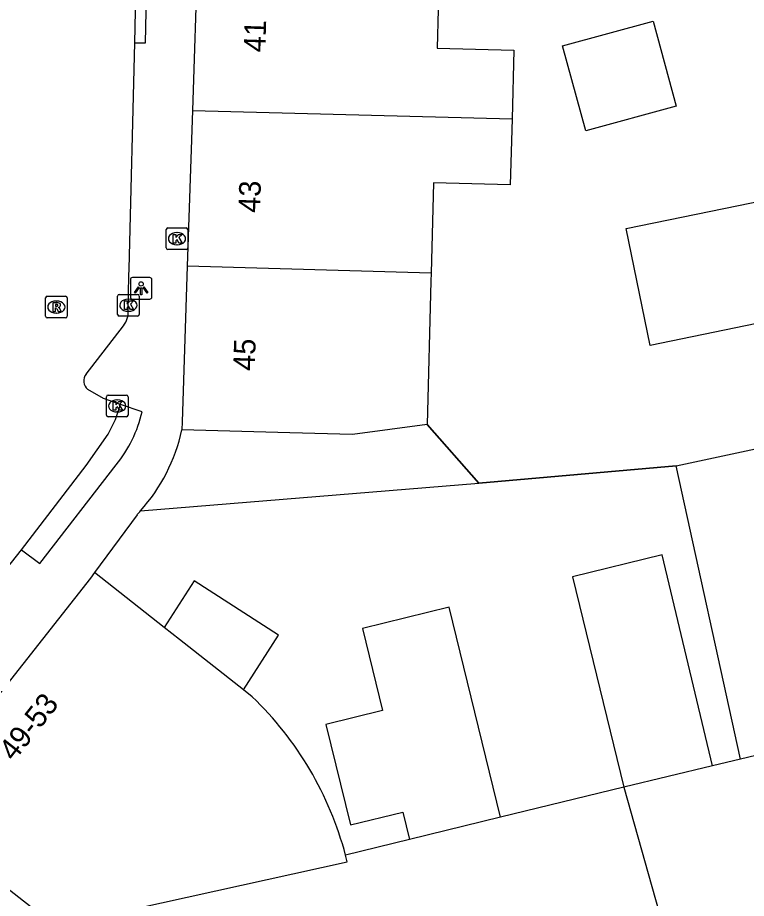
# Model space of a CAD drawing. Extents: x 162074 to 163034, y 381824 to 382557.
# Drawn here: x 162219.38 to 162253.14, y 382105.9 to 382146.68 of the extents above; entities that cross this region are included whole.
import ezdxf

# ---------------------------------------------------------------- set-up
doc = ezdxf.new("R2010")
doc.units = 0
for name, color, linetype in [('IMGEO_Hek', 7, 'Continuous'), ('IMGEO_Kolk', 7, 'Continuous'), ('IMGEO_Lichtpunt', 7, 'Continuous'), ('IMGEO_Pand', 7, 'Continuous'), ('IMGEO_Pand_nummerreeks', 7, 'Continuous'), ('IMGEO_Rijbaan_lokaal_open', 7, 'Continuous'), ('IMGEO_Rioolput', 7, 'Continuous'), ('IMGEO_Voetpad_open', 7, 'Continuous')]:
    doc.layers.add(name, color=color, linetype=linetype)

msp = doc.modelspace()

# ---------------------------------------------------------------- linework, layer by layer
at = {"layer": 'IMGEO_Hek'}
msp.add_lwpolyline([(162249.896, 382125.928), (162240.742, 382125.127), (162238.357, 382127.847)], dxfattribs=at)
at = {"layer": 'IMGEO_Kolk'}
for p, q in [((162226.267, 382136.018), (162226.267, 382136.87)), ((162226.342, 382136.944), (162227.194, 382136.944)), ((162226.755, 382136.724), (162226.78, 382136.724)), ((162227.268, 382136.87), (162227.268, 382136.018)), ((162227.194, 382135.944), (162226.342, 382135.944)), ((162226.778, 382136.164), (162226.753, 382136.164)), ((162224.089, 382133.862), (162224.941, 382133.862)), ((162224.014, 382132.936), (162224.014, 382133.788)), ((162224.502, 382133.642), (162224.527, 382133.642)), ((162225.015, 382133.788), (162225.015, 382132.936)), ((162224.525, 382133.082), (162224.5, 382133.082)), ((162224.941, 382132.862), (162224.089, 382132.862)), ((162223.497, 382128.274), (162223.497, 382129.126)), ((162223.572, 382129.2), (162224.424, 382129.2)), ((162223.985, 382128.98), (162224.01, 382128.98)), ((162224.498, 382129.126), (162224.498, 382128.274)), ((162224.424, 382128.2), (162223.572, 382128.2)), ((162224.008, 382128.42), (162223.983, 382128.42))]:
    msp.add_line(p, q, dxfattribs=at)
for points in [[(162226.267, 382136.018), (162226.267, 382136.87)], [(162226.342, 382136.944), (162227.194, 382136.944)], [(162227.268, 382136.87), (162227.268, 382136.018)], [(162226.588, 382136.644), (162226.711, 382136.644), (162226.711, 382136.493), (162226.841, 382136.644), (162227.005, 382136.644), (162226.859, 382136.493), (162227.012, 382136.244), (162226.86, 382136.244), (162226.775, 382136.408), (162226.711, 382136.341), (162226.711, 382136.244), (162226.588, 382136.244), (162226.588, 382136.644)], [(162227.194, 382135.944), (162226.342, 382135.944)], [(162224.089, 382133.862), (162224.941, 382133.862)], [(162224.014, 382132.936), (162224.014, 382133.788)], [(162224.335, 382133.562), (162224.458, 382133.562), (162224.458, 382133.411), (162224.588, 382133.562), (162224.752, 382133.562), (162224.606, 382133.411), (162224.759, 382133.162), (162224.607, 382133.162), (162224.522, 382133.326), (162224.458, 382133.259), (162224.458, 382133.162), (162224.335, 382133.162), (162224.335, 382133.562)], [(162225.015, 382133.788), (162225.015, 382132.936)], [(162224.941, 382132.862), (162224.089, 382132.862)], [(162223.497, 382128.274), (162223.497, 382129.126)], [(162223.572, 382129.2), (162224.424, 382129.2)], [(162224.498, 382129.126), (162224.498, 382128.274)], [(162223.818, 382128.9), (162223.941, 382128.9), (162223.941, 382128.749), (162224.071, 382128.9), (162224.235, 382128.9), (162224.089, 382128.749), (162224.242, 382128.5), (162224.09, 382128.5), (162224.005, 382128.664), (162223.941, 382128.597), (162223.941, 382128.5), (162223.818, 382128.5), (162223.818, 382128.9)], [(162224.424, 382128.2), (162223.572, 382128.2)]]:
    msp.add_lwpolyline(points, dxfattribs=at)
for centre, start, end in [((162226.344, 382136.868), 91.552, 178.448), ((162226.344, 382136.868), 91.552, 178.448), ((162227.192, 382136.868), 1.552, 88.448), ((162227.192, 382136.868), 1.552, 88.448), ((162226.344, 382136.02), 181.552, 268.448), ((162226.344, 382136.02), 181.552, 268.448), ((162227.192, 382136.02), 271.552, 358.448), ((162227.192, 382136.02), 271.552, 358.448), ((162224.091, 382133.786), 91.552, 178.448), ((162224.091, 382133.786), 91.552, 178.448), ((162224.939, 382133.786), 1.552, 88.448), ((162224.939, 382133.786), 1.552, 88.448), ((162224.091, 382132.938), 181.552, 268.448), ((162224.091, 382132.938), 181.552, 268.448), ((162224.939, 382132.938), 271.552, 358.448), ((162224.939, 382132.938), 271.552, 358.448), ((162223.574, 382129.124), 91.552, 178.448), ((162223.574, 382129.124), 91.552, 178.448), ((162224.422, 382129.124), 1.552, 88.448), ((162224.422, 382129.124), 1.552, 88.448), ((162223.574, 382128.276), 181.552, 268.448), ((162223.574, 382128.276), 181.552, 268.448), ((162224.422, 382128.276), 271.552, 358.448), ((162224.422, 382128.276), 271.552, 358.448)]:
    msp.add_arc(centre, 0.0765, start, end, dxfattribs=at)
for centre, major_axis, ratio, start_param, end_param in [((162226.754, 382136.444), (-0.387, 0.002), 0.722429, 4.712389, 7.853982), ((162226.779, 382136.444), (-0.39, 0.002), 0.717154, 1.570796, 4.712389), ((162224.501, 382133.362), (-0.387, 0.002), 0.722429, 4.712389, 7.853982), ((162224.526, 382133.362), (-0.39, 0.002), 0.717154, 1.570796, 4.712389), ((162223.984, 382128.7), (-0.387, 0.002), 0.722429, 4.712389, 7.853982), ((162224.009, 382128.7), (-0.39, 0.002), 0.717154, 1.570796, 4.712389)]:
    msp.add_ellipse(centre, major_axis=major_axis, ratio=ratio, start_param=start_param, end_param=end_param, dxfattribs=at)
at = {"layer": 'IMGEO_Lichtpunt'}
for p, q in [((162225.51, 382134.647), (162224.702, 382134.647)), ((162225.51, 382134.647), (162224.702, 382134.647)), ((162224.608, 382134.552), (162224.608, 382133.745)), ((162224.608, 382134.552), (162224.608, 382133.745)), ((162225.604, 382133.745), (162225.604, 382134.552)), ((162225.604, 382133.745), (162225.604, 382134.552)), ((162224.702, 382133.651), (162225.51, 382133.651)), ((162224.702, 382133.651), (162225.51, 382133.651))]:
    msp.add_line(p, q, dxfattribs=at)
for points in [[(162224.982, 382134.216), (162225.021, 382134.188), (162224.833, 382133.926), (162224.795, 382133.953), (162224.982, 382134.216)], [(162225.084, 382134.168), (162225.131, 382134.168), (162225.131, 382133.846), (162225.084, 382133.846), (162225.084, 382134.168)], [(162225.194, 382134.188), (162225.232, 382134.215), (162225.419, 382133.953), (162225.38, 382133.925), (162225.194, 382134.188)]]:
    msp.add_lwpolyline(points, dxfattribs=at)
msp.add_circle((162225.107, 382134.35), 0.0994, dxfattribs=at)
for centre, start, end in [((162224.702, 382134.552), 90, 180), ((162224.702, 382134.552), 90, 180), ((162225.51, 382134.552), 0, 90), ((162225.51, 382134.552), 0, 90), ((162224.702, 382133.745), 180, 270), ((162224.702, 382133.745), 180, 270), ((162225.51, 382133.745), 270, 0), ((162225.51, 382133.745), 270, 360)]:
    msp.add_arc(centre, 0.0946, start, end, dxfattribs=at)
at = {"layer": 'IMGEO_Pand'}
for points in [[(162227.718, 382149.559), (162227.482, 382142.373)], [(162238.919, 382149.247), (162238.909, 382148.867), (162238.815, 382145.272), (162242.369, 382145.178), (162242.285, 382142.001)], [(162249.888, 382142.587), (162245.698, 382141.445), (162244.626, 382145.374), (162248.817, 382146.517), (162249.888, 382142.587)], [(162227.482, 382142.373), (162227.245, 382135.171)], [(162227.482, 382142.373), (162242.285, 382142.001)], [(162242.285, 382142.001), (162242.205, 382138.94), (162238.651, 382139.03), (162238.541, 382134.851)], [(162259.857, 382139.434), (162260.967, 382134.028), (162248.684, 382131.506), (162247.574, 382136.911), (162259.857, 382139.434)], [(162227.245, 382135.171), (162227.008, 382127.961), (162226.996, 382127.589)], [(162238.541, 382134.851), (162227.245, 382135.171)], [(162238.541, 382134.851), (162238.531, 382134.472), (162238.357, 382127.847)], [(162249.896, 382125.928), (162266.45, 382129.481)], [(162238.357, 382127.847), (162234.894, 382127.382), (162231.995, 382127.458), (162226.996, 382127.589)], [(162252.869, 382112.342), (162249.896, 382125.928)], [(162222.952, 382120.984), (162222.754, 382120.733), (162212.028, 382107.113)], [(162226.174, 382118.447), (162222.952, 382120.984)], [(162229.842, 382115.558), (162226.88, 382117.891), (162226.174, 382118.447)], [(162270.814, 382116.639), (162252.869, 382112.342)], [(162230.255, 382115.232), (162229.842, 382115.558)], [(162252.869, 382112.342), (162251.579, 382112.033)], [(162251.579, 382112.033), (162247.469, 382111.049)], [(162247.469, 382111.049), (162251.349, 382097.252), (162247.365, 382094.399)], [(162216.468, 382103.337), (162218.874, 382106.407), (162221.161, 382104.607), (162226.044, 382105.686), (162234.656, 382107.59), (162234.577, 382107.901)]]:
    msp.add_lwpolyline(points, dxfattribs=at)
msp.add_arc((162219.291, 382103.829), 15.819, 14.9177, 46.1254, dxfattribs=at)
at = {"layer": 'IMGEO_Rijbaan_lokaal_open'}
for points in [[(162224.817, 382145.516), (162224.918, 382150.646)], [(162224.511, 382133.117), (162224.54, 382134.723), (162224.549, 382135.054), (162224.817, 382145.516)], [(162222.559, 382130.179), (162224.285, 382132.416)], [(162224.144, 382128.773), (162223.363, 382129.047), (162222.639, 382129.465)], [(162219.561, 382122.034), (162222.557, 382125.939), (162223.572, 382127.387), (162223.916, 382128.078), (162224.144, 382128.773)], [(162240.742, 382125.127), (162249.896, 382125.928)], [(162225.079, 382123.843), (162240.742, 382125.127)], [(162224.917, 382123.666), (162222.952, 382120.984)], [(162210.136, 382109.839), (162214.639, 382115.486), (162218.226, 382120.357), (162219.561, 382122.034)], [(162251.579, 382112.033), (162249.239, 382121.806), (162245.09, 382120.793), (162247.469, 382111.049)], [(162229.842, 382115.558), (162231.473, 382118.081), (162227.569, 382120.605), (162226.174, 382118.447)], [(162241.75, 382109.653), (162239.375, 382119.38), (162235.354, 382118.399), (162236.283, 382114.594), (162233.665, 382113.955), (162234.802, 382109.299), (162237.221, 382109.89), (162237.531, 382108.622)], [(162247.469, 382111.049), (162241.75, 382109.653)], [(162241.75, 382109.653), (162237.531, 382108.622)], [(162237.531, 382108.622), (162234.577, 382107.901)]]:
    msp.add_lwpolyline(points, dxfattribs=at)
for centre, radius, start, end in [((162223.527, 382133.047), 0.986, 320.2108, 4.0509), ((162222.939, 382129.86), 0.496, 140.0001, 232.7859), ((162220.061, 382128.273), 6.693, 316.5065, 318.5606)]:
    msp.add_arc(centre, radius, start, end, dxfattribs=at)
at = {"layer": 'IMGEO_Rioolput'}
for p, q in [((162220.678, 382132.853), (162220.678, 382133.705)), ((162220.753, 382133.779), (162221.605, 382133.779)), ((162221.166, 382133.559), (162221.191, 382133.559)), ((162221.679, 382133.705), (162221.679, 382132.853)), ((162221.189, 382132.999), (162221.164, 382132.999)), ((162221.605, 382132.779), (162220.753, 382132.779))]:
    msp.add_line(p, q, dxfattribs=at)
for points in [[(162220.678, 382132.853), (162220.678, 382133.705)], [(162220.753, 382133.779), (162221.605, 382133.779)], [(162221.267, 382133.477), (162221.015, 382133.479), (162221.015, 382133.079)], [(162221.679, 382133.705), (162221.679, 382132.853)], [(162221.015, 382133.079), (162221.139, 382133.079), (162221.139, 382133.241), (162221.15, 382133.241)], [(162221.193, 382133.398), (162221.139, 382133.398), (162221.139, 382133.317)], [(162221.139, 382133.317), (162221.191, 382133.317)], [(162221.197, 382133.212), (162221.268, 382133.079), (162221.408, 382133.079), (162221.343, 382133.205)], [(162221.605, 382132.779), (162220.753, 382132.779)]]:
    msp.add_lwpolyline(points, dxfattribs=at)
for centre, radius, start, end in [((162220.755, 382133.703), 0.0765, 91.552, 178.448), ((162220.755, 382133.703), 0.0765, 91.552, 178.448), ((162221.266, 382133.367), 0.109, 350.3612, 89.416), ((162221.603, 382133.703), 0.0765, 1.552, 88.448), ((162221.603, 382133.703), 0.0765, 1.552, 88.448), ((162221.149, 382133.188), 0.0533, 26.0293, 88.6989), ((162221.175, 382133.506), 0.19, 274.7715, 282.9687), ((162221.199, 382133.302), 0.0964, 77.0061, 93.1865), ((162221.213, 382133.359), 0.0378, 276.6634, 79.6772), ((162221.264, 382133.367), 0.112, 277.5842, 350.9817), ((162221.248, 382133.152), 0.108, 29.5134, 73.7905), ((162220.755, 382132.855), 0.0765, 181.552, 268.448), ((162220.755, 382132.855), 0.0765, 181.552, 268.448), ((162221.603, 382132.855), 0.0765, 271.552, 358.448), ((162221.603, 382132.855), 0.0765, 271.552, 358.448)]:
    msp.add_arc(centre, radius, start, end, dxfattribs=at)
for centre, major_axis, ratio, start_param, end_param in [((162221.165, 382133.279), (-0.387, 0.002), 0.722429, 4.712389, 7.853982), ((162221.19, 382133.279), (-0.39, 0.002), 0.717154, 1.570796, 4.712389)]:
    msp.add_ellipse(centre, major_axis=major_axis, ratio=ratio, start_param=start_param, end_param=end_param, dxfattribs=at)
at = {"layer": 'IMGEO_Voetpad_open'}
for points in [[(162224.817, 382145.516), (162225.316, 382145.507), (162225.417, 382150.637), (162224.918, 382150.646)], [(162225.154, 382128.434), (162224.144, 382128.773)], [(162238.357, 382127.847), (162240.742, 382125.127)], [(162219.561, 382122.034), (162220.408, 382121.399), (162223.957, 382125.973)]]:
    msp.add_lwpolyline(points, dxfattribs=at)
for centre, radius, start, end in [((162219.161, 382129.827), 6.153, 321.2135, 346.9111), ((162218.82, 382129.41), 8.377, 318.3522, 347.446)]:
    msp.add_arc(centre, radius, start, end, dxfattribs=at)

# ---------------------------------------------------------------- texts
at = {"layer": 'IMGEO_Pand_nummerreeks'}
for s, rotation, p in [('41', 88.1152, (162230.852, 382145.064)), ('43', 88.1177, (162230.608, 382137.632)), ('45', 88.1152, (162230.367, 382130.315)), ('49-53', 51.7782, (162219.218, 382112.203))]:
    msp.add_text(s, height=1, rotation=rotation, dxfattribs=at).set_placement(p)

doc.saveas('drawing.dxf')
